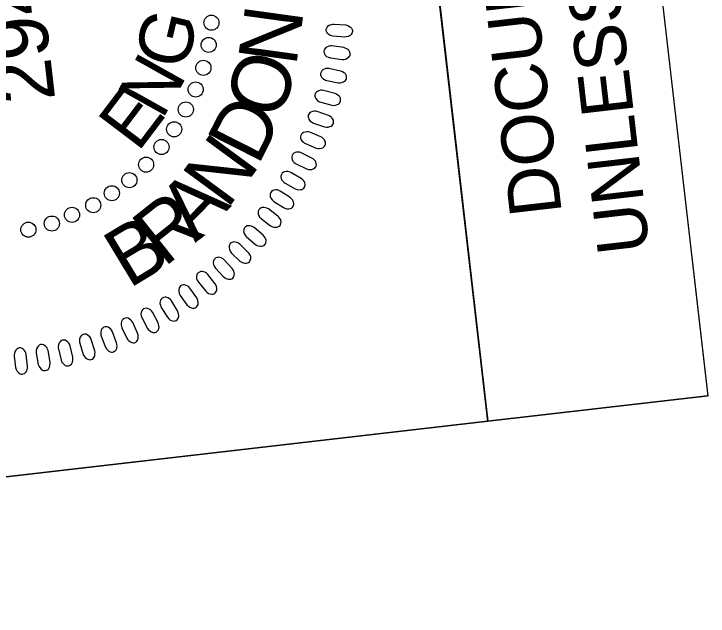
# Model space of a CAD drawing. Extents: x 477607 to 479438, y 495543 to 499482.
# Drawn here: x 477755.3 to 477829, y 497193.8 to 497257.7 of the extents above; entities that cross this region are included whole.
import ezdxf

# ---------------------------------------------------------------- set-up
doc = ezdxf.new("R2010")
doc.units = 0
for name, color, linetype in [('Sheet Border Standard 30in CELL', 7, 'Continuous'), ('Sheet Layout Plan Border', 7, 'Continuous'), ('Sheet PE Seal Cell', 7, 'Continuous'), ('Sheet Plan CELL', 7, 'Continuous'), ('Sheet Sticker Exception Certification CELL', 7, 'Continuous')]:
    doc.layers.add(name, color=color, linetype=linetype)

msp = doc.modelspace()

# ---------------------------------------------------------------- linework, layer by layer
at = {"layer": 'Sheet Border Standard 30in CELL'}
msp.add_lwpolyline([(477693.829, 497201.611), (477682.369, 497301.002), (477794.128, 497313.888), (477805.588, 497214.497)], close=True, dxfattribs=at)
at = {"layer": 'Sheet Layout Plan Border'}
msp.add_lwpolyline([(478060.611, 495968.966), (478655.257, 496063.069), (478848.534, 496026.024), (478735.995, 497002.058), (478709.928, 496998.314), (478420.128, 496964.9), (478384.13, 497277.103), (478673.93, 497310.517), (478699.758, 497316.337), (478696.236, 497346.887), (478616.747, 497337.721), (478607.505, 497417.875), (478188.47, 497393.351), (477955.381, 497379.709), (477811.168, 497371.269), (477828.931, 497217.213), (477697.933, 497202.084), (477716.324, 497043.314), (477674.836, 497038.508), (477805.454, 495905.894)], close=True, dxfattribs=at)
msp.add_lwpolyline([(478060.611, 495968.966), (478655.257, 496063.069), (478848.534, 496026.024), (478735.995, 497002.058), (478709.928, 496998.314), (478420.128, 496964.9), (478384.13, 497277.103), (478673.93, 497310.517), (478699.758, 497316.337), (478696.236, 497346.887), (478616.747, 497337.721), (478607.505, 497417.875), (478188.47, 497393.351), (477955.381, 497379.709), (477811.168, 497371.269), (477828.931, 497217.213), (477697.933, 497202.084), (477716.324, 497043.314), (477674.836, 497038.508), (477805.454, 495905.894)], close=True, dxfattribs=at)
at = {"layer": 'Sheet PE Seal Cell'}
for points in [[(477789.283, 497256.661), (477790.507, 497256.57), (477790.722, 497256.517), (477790.858, 497256.454), (477791.019, 497256.33), (477791.121, 497256.224), (477791.192, 497256.107), (477791.225, 497256), (477791.236, 497255.886), (477791.208, 497255.776), (477791.169, 497255.659), (477791.102, 497255.559), (477790.995, 497255.462), (477790.911, 497255.408), (477790.756, 497255.352), (477790.573, 497255.306), (477790.412, 497255.295), (477789.159, 497255.381), (477788.991, 497255.416), (477788.855, 497255.471), (477788.703, 497255.572), (477788.572, 497255.694), (477788.499, 497255.797), (477788.451, 497255.958), (477788.443, 497256.109), (477788.494, 497256.254), (477788.551, 497256.356), (477788.659, 497256.475), (477788.837, 497256.581), (477789.022, 497256.635), (477789.152, 497256.655)], [(477788.904, 497253.072), (477790.12, 497252.904), (477790.341, 497252.912), (477790.487, 497252.944), (477790.671, 497253.032), (477790.793, 497253.113), (477790.887, 497253.214), (477790.941, 497253.312), (477790.976, 497253.42), (477790.971, 497253.534), (477790.957, 497253.657), (477790.913, 497253.768), (477790.828, 497253.885), (477790.758, 497253.956), (477790.618, 497254.042), (477790.449, 497254.126), (477790.294, 497254.17), (477789.05, 497254.35), (477788.879, 497254.35), (477788.734, 497254.324), (477788.564, 497254.257), (477788.411, 497254.166), (477788.318, 497254.08), (477788.237, 497253.933), (477788.198, 497253.788), (477788.217, 497253.633), (477788.252, 497253.523), (477788.333, 497253.384), (477788.485, 497253.242), (477788.654, 497253.151), (477788.778, 497253.104)], [(477788.503, 497250.677), (477789.705, 497250.434), (477789.928, 497250.427), (477790.075, 497250.45), (477790.264, 497250.526), (477790.39, 497250.6), (477790.491, 497250.695), (477790.55, 497250.788), (477790.592, 497250.895), (477790.595, 497251.009), (477790.589, 497251.132), (477790.552, 497251.246), (477790.474, 497251.369), (477790.408, 497251.443), (477790.275, 497251.539), (477790.111, 497251.633), (477789.959, 497251.687), (477788.729, 497251.943), (477788.558, 497251.955), (477788.412, 497251.938), (477788.238, 497251.882), (477788.079, 497251.8), (477787.981, 497251.72), (477787.892, 497251.579), (477787.842, 497251.436), (477787.852, 497251.281), (477787.881, 497251.169), (477787.952, 497251.025), (477788.095, 497250.874), (477788.258, 497250.772), (477788.379, 497250.718)], [(477787.859, 497248.38), (477789.044, 497248.061), (477789.266, 497248.04), (477789.414, 497248.054), (477789.608, 497248.119), (477789.739, 497248.184), (477789.844, 497248.272), (477789.91, 497248.362), (477789.959, 497248.466), (477789.968, 497248.579), (477789.97, 497248.703), (477789.941, 497248.819), (477789.87, 497248.946), (477789.809, 497249.024), (477789.682, 497249.128), (477789.525, 497249.232), (477789.376, 497249.296), (477788.164, 497249.629), (477787.995, 497249.651), (477787.849, 497249.643), (477787.671, 497249.599), (477787.507, 497249.527), (477787.405, 497249.453), (477787.306, 497249.318), (477787.248, 497249.178), (477787.249, 497249.024), (477787.27, 497248.91), (477787.332, 497248.761), (477787.465, 497248.602), (477787.622, 497248.49), (477787.739, 497248.428)], [(477787.102, 497246.151), (477788.264, 497245.759), (477788.484, 497245.724), (477788.633, 497245.729), (477788.83, 497245.781), (477788.965, 497245.838), (477789.076, 497245.918), (477789.147, 497246.004), (477789.202, 497246.105), (477789.218, 497246.217), (477789.229, 497246.34), (477789.206, 497246.458), (477789.144, 497246.59), (477789.088, 497246.672), (477788.968, 497246.783), (477788.817, 497246.898), (477788.673, 497246.97), (477787.485, 497247.379), (477787.316, 497247.411), (477787.17, 497247.413), (477786.99, 497247.38), (477786.822, 497247.318), (477786.715, 497247.251), (477786.608, 497247.122), (477786.541, 497246.986), (477786.531, 497246.832), (477786.546, 497246.717), (477786.599, 497246.565), (477786.721, 497246.398), (477786.871, 497246.276), (477786.984, 497246.207)], [(477786.238, 497243.978), (477787.374, 497243.514), (477787.591, 497243.465), (477787.74, 497243.46), (477787.94, 497243.5), (477788.078, 497243.549), (477788.194, 497243.622), (477788.271, 497243.704), (477788.332, 497243.801), (477788.355, 497243.911), (477788.373, 497244.033), (477788.358, 497244.153), (477788.304, 497244.288), (477788.254, 497244.373), (477788.14, 497244.492), (477787.997, 497244.616), (477787.858, 497244.697), (477786.697, 497245.179), (477786.532, 497245.222), (477786.385, 497245.234), (477786.204, 497245.211), (477786.032, 497245.161), (477785.922, 497245.101), (477785.807, 497244.978), (477785.732, 497244.847), (477785.713, 497244.694), (477785.719, 497244.578), (477785.763, 497244.422), (477785.875, 497244.248), (477786.016, 497244.117), (477786.124, 497244.041)], [(477785.262, 497241.834), (477786.367, 497241.3), (477786.58, 497241.237), (477786.728, 497241.223), (477786.93, 497241.25), (477787.071, 497241.29), (477787.191, 497241.356), (477787.274, 497241.433), (477787.34, 497241.526), (477787.371, 497241.635), (477787.397, 497241.756), (477787.388, 497241.876), (477787.344, 497242.013), (477787.298, 497242.102), (477787.193, 497242.228), (477787.057, 497242.36), (477786.924, 497242.45), (477785.796, 497243.004), (477785.633, 497243.058), (477785.488, 497243.078), (477785.305, 497243.067), (477785.131, 497243.027), (477785.017, 497242.974), (477784.894, 497242.859), (477784.812, 497242.733), (477784.782, 497242.581), (477784.781, 497242.465), (477784.815, 497242.308), (477784.916, 497242.126), (477785.049, 497241.987), (477785.152, 497241.904)], [(477784.076, 497239.783), (477785.145, 497239.18), (477785.354, 497239.105), (477785.501, 497239.082), (477785.704, 497239.096), (477785.848, 497239.127), (477785.972, 497239.185), (477786.058, 497239.256), (477786.131, 497239.345), (477786.168, 497239.452), (477786.201, 497239.571), (477786.201, 497239.692), (477786.165, 497239.832), (477786.125, 497239.923), (477786.027, 497240.055), (477785.901, 497240.195), (477785.773, 497240.293), (477784.682, 497240.917), (477784.524, 497240.981), (477784.38, 497241.01), (477784.197, 497241.011), (477784.02, 497240.983), (477783.903, 497240.937), (477783.773, 497240.83), (477783.682, 497240.709), (477783.644, 497240.559), (477783.636, 497240.443), (477783.66, 497240.284), (477783.749, 497240.097), (477783.873, 497239.949), (477783.971, 497239.86)], [(477782.889, 497237.853), (477783.917, 497237.184), (477784.122, 497237.096), (477784.267, 497237.063), (477784.47, 497237.065), (477784.615, 497237.087), (477784.743, 497237.137), (477784.834, 497237.203), (477784.912, 497237.287), (477784.956, 497237.391), (477784.996, 497237.508), (477785.003, 497237.628), (477784.976, 497237.771), (477784.943, 497237.864), (477784.854, 497238.002), (477784.736, 497238.15), (477784.614, 497238.256), (477783.565, 497238.947), (477783.41, 497239.021), (477783.268, 497239.059), (477783.086, 497239.071), (477782.908, 497239.054), (477782.788, 497239.015), (477782.653, 497238.916), (477782.554, 497238.802), (477782.506, 497238.655), (477782.491, 497238.539), (477782.505, 497238.379), (477782.582, 497238.187), (477782.696, 497238.031), (477782.788, 497237.936)], [(477781.562, 497235.999), (477782.547, 497235.267), (477782.745, 497235.166), (477782.888, 497235.125), (477783.091, 497235.113), (477783.238, 497235.126), (477783.368, 497235.168), (477783.462, 497235.228), (477783.545, 497235.307), (477783.596, 497235.408), (477783.643, 497235.523), (477783.658, 497235.642), (477783.64, 497235.785), (477783.612, 497235.881), (477783.533, 497236.025), (477783.424, 497236.179), (477783.31, 497236.293), (477782.305, 497237.049), (477782.156, 497237.132), (477782.017, 497237.179), (477781.836, 497237.202), (477781.657, 497237.196), (477781.535, 497237.165), (477781.393, 497237.075), (477781.287, 497236.967), (477781.231, 497236.823), (477781.209, 497236.709), (477781.212, 497236.548), (477781.277, 497236.351), (477781.381, 497236.189), (477781.467, 497236.088)], [(477779.994, 497234.072), (477780.931, 497233.279), (477781.122, 497233.166), (477781.262, 497233.115), (477781.465, 497233.091), (477781.611, 497233.095), (477781.745, 497233.129), (477781.843, 497233.183), (477781.93, 497233.256), (477781.987, 497233.355), (477782.042, 497233.465), (477782.064, 497233.583), (477782.055, 497233.728), (477782.033, 497233.825), (477781.962, 497233.973), (477781.864, 497234.135), (477781.757, 497234.255), (477780.802, 497235.072), (477780.658, 497235.165), (477780.522, 497235.22), (477780.343, 497235.256), (477780.164, 497235.26), (477780.041, 497235.237), (477779.893, 497235.156), (477779.781, 497235.054), (477779.715, 497234.915), (477779.686, 497234.803), (477779.68, 497234.641), (477779.732, 497234.441), (477779.826, 497234.273), (477779.905, 497234.167)], [(477778.409, 497232.369), (477779.294, 497231.519), (477779.477, 497231.394), (477779.614, 497231.335), (477779.814, 497231.298), (477779.961, 497231.292), (477780.096, 497231.318), (477780.197, 497231.366), (477780.289, 497231.433), (477780.352, 497231.527), (477780.413, 497231.635), (477780.443, 497231.751), (477780.443, 497231.896), (477780.427, 497231.994), (477780.366, 497232.147), (477780.278, 497232.314), (477780.179, 497232.441), (477779.277, 497233.317), (477779.14, 497233.418), (477779.007, 497233.482), (477778.831, 497233.528), (477778.652, 497233.544), (477778.527, 497233.529), (477778.375, 497233.457), (477778.257, 497233.363), (477778.183, 497233.228), (477778.146, 497233.118), (477778.13, 497232.957), (477778.169, 497232.753), (477778.252, 497232.58), (477778.325, 497232.469)], [(477776.7, 497230.759), (477777.53, 497229.855), (477777.706, 497229.719), (477777.839, 497229.651), (477778.036, 497229.602), (477778.182, 497229.587), (477778.318, 497229.604), (477778.422, 497229.646), (477778.519, 497229.707), (477778.588, 497229.797), (477778.656, 497229.9), (477778.692, 497230.015), (477778.702, 497230.159), (477778.692, 497230.259), (477778.64, 497230.414), (477778.563, 497230.587), (477778.472, 497230.72), (477777.627, 497231.65), (477777.496, 497231.76), (477777.368, 497231.832), (477777.194, 497231.889), (477777.018, 497231.916), (477776.892, 497231.91), (477776.736, 497231.848), (477776.612, 497231.761), (477776.529, 497231.63), (477776.486, 497231.523), (477776.459, 497231.363), (477776.486, 497231.158), (477776.558, 497230.98), (477776.623, 497230.864)], [(477774.884, 497229.265), (477775.656, 497228.31), (477775.823, 497228.163), (477775.951, 497228.088), (477776.145, 497228.026), (477776.289, 497228.002), (477776.427, 497228.011), (477776.533, 497228.045), (477776.633, 497228.1), (477776.707, 497228.187), (477776.782, 497228.285), (477776.826, 497228.397), (477776.844, 497228.541), (477776.841, 497228.64), (477776.799, 497228.799), (477776.732, 497228.976), (477776.65, 497229.114), (477775.866, 497230.096), (477775.742, 497230.214), (477775.618, 497230.294), (477775.449, 497230.362), (477775.274, 497230.4), (477775.148, 497230.401), (477774.988, 497230.349), (477774.859, 497230.27), (477774.768, 497230.145), (477774.718, 497230.041), (477774.682, 497229.883), (477774.696, 497229.676), (477774.756, 497229.494), (477774.815, 497229.375)], [(477772.956, 497227.878), (477773.666, 497226.877), (477773.823, 497226.721), (477773.947, 497226.637), (477774.136, 497226.563), (477774.279, 497226.53), (477774.416, 497226.53), (477774.525, 497226.558), (477774.628, 497226.607), (477774.707, 497226.688), (477774.788, 497226.782), (477774.839, 497226.891), (477774.866, 497227.033), (477774.869, 497227.133), (477774.837, 497227.293), (477774.782, 497227.474), (477774.709, 497227.618), (477773.987, 497228.647), (477773.87, 497228.772), (477773.753, 497228.86), (477773.588, 497228.938), (477773.416, 497228.987), (477773.29, 497228.996), (477773.128, 497228.954), (477772.994, 497228.883), (477772.895, 497228.764), (477772.838, 497228.663), (477772.793, 497228.508), (477772.794, 497228.301), (477772.842, 497228.115), (477772.893, 497227.992)], [(477770.941, 497226.592), (477771.587, 497225.548), (477771.734, 497225.382), (477771.852, 497225.29), (477772.037, 497225.206), (477772.177, 497225.163), (477772.315, 497225.154), (477772.424, 497225.176), (477772.53, 497225.218), (477772.615, 497225.294), (477772.701, 497225.382), (477772.759, 497225.488), (477772.795, 497225.628), (477772.804, 497225.727), (477772.782, 497225.89), (477772.738, 497226.074), (477772.674, 497226.221), (477772.019, 497227.294), (477771.91, 497227.426), (477771.799, 497227.521), (477771.639, 497227.609), (477771.47, 497227.67), (477771.345, 497227.686), (477771.18, 497227.655), (477771.042, 497227.593), (477770.937, 497227.48), (477770.874, 497227.382), (477770.818, 497227.231), (477770.806, 497227.024), (477770.843, 497226.836), (477770.886, 497226.71)], [(477768.899, 497225.451), (477769.478, 497224.369), (477769.615, 497224.193), (477769.726, 497224.094), (477769.905, 497223.998), (477770.043, 497223.947), (477770.18, 497223.93), (477770.29, 497223.944), (477770.399, 497223.979), (477770.488, 497224.05), (477770.579, 497224.133), (477770.643, 497224.234), (477770.688, 497224.372), (477770.704, 497224.47), (477770.692, 497224.635), (477770.66, 497224.82), (477770.605, 497224.972), (477770.019, 497226.083), (477769.919, 497226.223), (477769.813, 497226.324), (477769.659, 497226.422), (477769.494, 497226.493), (477769.371, 497226.517), (477769.204, 497226.496), (477769.063, 497226.443), (477768.95, 497226.337), (477768.881, 497226.244), (477768.816, 497226.096), (477768.791, 497225.89), (477768.816, 497225.7), (477768.851, 497225.572)], [(477766.764, 497224.441), (477767.274, 497223.325), (477767.399, 497223.141), (477767.504, 497223.035), (477767.677, 497222.928), (477767.811, 497222.868), (477767.946, 497222.843), (477768.057, 497222.85), (477768.168, 497222.878), (477768.261, 497222.943), (477768.358, 497223.02), (477768.428, 497223.118), (477768.481, 497223.252), (477768.503, 497223.349), (477768.502, 497223.513), (477768.482, 497223.702), (477768.436, 497223.856), (477767.92, 497225.002), (477767.829, 497225.147), (477767.73, 497225.255), (477767.583, 497225.363), (477767.423, 497225.443), (477767.301, 497225.476), (477767.134, 497225.465), (477766.989, 497225.421), (477766.87, 497225.322), (477766.795, 497225.234), (477766.721, 497225.09), (477766.683, 497224.886), (477766.696, 497224.695), (477766.723, 497224.565)], [(477764.57, 497223.53), (477765.008, 497222.384), (477765.122, 497222.193), (477765.22, 497222.08), (477765.386, 497221.962), (477765.516, 497221.895), (477765.649, 497221.861), (477765.761, 497221.861), (477765.873, 497221.882), (477765.97, 497221.941), (477766.071, 497222.011), (477766.148, 497222.104), (477766.21, 497222.236), (477766.237, 497222.331), (477766.247, 497222.495), (477766.238, 497222.684), (477766.202, 497222.841), (477765.76, 497224.017), (477765.678, 497224.168), (477765.586, 497224.282), (477765.445, 497224.399), (477765.291, 497224.489), (477765.172, 497224.529), (477765.003, 497224.529), (477764.856, 497224.494), (477764.731, 497224.403), (477764.651, 497224.319), (477764.568, 497224.18), (477764.518, 497223.98), (477764.518, 497223.787), (477764.538, 497223.656)], [(477762.299, 497222.785), (477762.665, 497221.614), (477762.766, 497221.416), (477762.857, 497221.298), (477763.015, 497221.169), (477763.141, 497221.094), (477763.271, 497221.051), (477763.383, 497221.045), (477763.496, 497221.059), (477763.597, 497221.111), (477763.702, 497221.176), (477763.785, 497221.264), (477763.854, 497221.391), (477763.888, 497221.484), (477763.908, 497221.647), (477763.911, 497221.837), (477763.885, 497221.995), (477763.517, 497223.197), (477763.445, 497223.352), (477763.36, 497223.472), (477763.227, 497223.597), (477763.078, 497223.697), (477762.962, 497223.745), (477762.795, 497223.755), (477762.645, 497223.729), (477762.515, 497223.647), (477762.43, 497223.568), (477762.338, 497223.435), (477762.275, 497223.237), (477762.264, 497223.045), (477762.275, 497222.913)], [(477760.027, 497222.187), (477760.318, 497220.996), (477760.407, 497220.792), (477760.491, 497220.668), (477760.64, 497220.53), (477760.761, 497220.447), (477760.889, 497220.396), (477761, 497220.383), (477761.114, 497220.39), (477761.217, 497220.436), (477761.327, 497220.493), (477761.415, 497220.576), (477761.492, 497220.698), (477761.531, 497220.79), (477761.561, 497220.951), (477761.576, 497221.14), (477761.56, 497221.3), (477761.269, 497222.522), (477761.207, 497222.681), (477761.129, 497222.806), (477761.005, 497222.94), (477760.863, 497223.049), (477760.75, 497223.104), (477760.583, 497223.124), (477760.433, 497223.108), (477760.297, 497223.034), (477760.207, 497222.96), (477760.107, 497222.833), (477760.032, 497222.64), (477760.009, 497222.45), (477760.011, 497222.317)], [(477755.344, 497221.429), (477755.484, 497220.21), (477755.547, 497219.997), (477755.614, 497219.864), (477755.745, 497219.708), (477755.854, 497219.61), (477755.975, 497219.544), (477756.083, 497219.516), (477756.197, 497219.509), (477756.306, 497219.542), (477756.421, 497219.585), (477756.519, 497219.656), (477756.611, 497219.768), (477756.661, 497219.854), (477756.711, 497220.01), (477756.75, 497220.195), (477756.754, 497220.356), (477756.618, 497221.606), (477756.577, 497221.771), (477756.516, 497221.905), (477756.408, 497222.053), (477756.281, 497222.179), (477756.176, 497222.247), (477756.013, 497222.289), (477755.862, 497222.291), (477755.718, 497222.234), (477755.62, 497222.173), (477755.504, 497222.06), (477755.405, 497221.878), (477755.359, 497221.692), (477755.344, 497221.559)], [(477757.68, 497221.751), (477757.896, 497220.543), (477757.972, 497220.334), (477758.048, 497220.206), (477758.189, 497220.059), (477758.304, 497219.967), (477758.428, 497219.909), (477758.538, 497219.888), (477758.652, 497219.889), (477758.758, 497219.928), (477758.871, 497219.979), (477758.964, 497220.056), (477759.049, 497220.173), (477759.094, 497220.262), (477759.133, 497220.42), (477759.161, 497220.608), (477759.155, 497220.768), (477758.94, 497222.007), (477758.888, 497222.17), (477758.82, 497222.299), (477758.703, 497222.441), (477758.568, 497222.558), (477758.459, 497222.62), (477758.294, 497222.651), (477758.143, 497222.644), (477758.003, 497222.579), (477757.908, 497222.511), (477757.801, 497222.391), (477757.713, 497222.203), (477757.679, 497222.014), (477757.672, 497221.881)]]:
    msp.add_lwpolyline(points, close=True, dxfattribs=at)
for centre in [(477776.264, 497256.812), (477775.974, 497254.454), (477775.411, 497252.025), (477774.592, 497249.727), (477773.553, 497247.603), (477772.312, 497245.497), (477770.964, 497243.619), (477769.334, 497241.748), (477767.559, 497240.101), (477765.702, 497238.711), (477763.723, 497237.441), (477761.474, 497236.421), (477759.335, 497235.494), (477756.843, 497234.847)]:
    msp.add_circle(centre, 0.801, dxfattribs=at)
at = {"layer": 'Sheet Plan CELL'}
for points in [[(478848.516, 496026.186), (477805.454, 495905.894), (477656.512, 497197.321), (477805.585, 497214.522), (477782.685, 497413.244), (478676.699, 497516.326)], [(477693.84, 497201.625), (477682.38, 497301.016), (477794.152, 497313.904), (477805.585, 497214.522)]]:
    msp.add_lwpolyline(points, close=True, dxfattribs=at)
at = {"layer": 'Sheet Sticker Exception Certification CELL'}
for p, q in [((477806.018, 497415.934), (477828.931, 497217.213)), ((477806.021, 497415.909), (477828.934, 497217.189)), ((477805.588, 497214.497), (477782.675, 497413.218)), ((477828.931, 497217.213), (477805.585, 497214.522)), ((477828.934, 497217.189), (477805.588, 497214.497))]:
    msp.add_line(p, q, dxfattribs=at)

# ---------------------------------------------------------------- texts
at = {"layer": 'Sheet PE Seal Cell'}
for s, height, rotation, p in [('29470', 6.2363, 96.55865, (477759.704, 497248.641)), ('N', 6.236, 82.12779, (477785.247, 497252.101)), ('G', 5.669, 76.66226, (477773.564, 497251.648)), ('N', 5.669, 60.78267, (477771.046, 497246.431)), ('O', 6.236, 72.02794, (477783.527, 497246.314)), ('E', 5.669, 52.84287, (477768.47, 497242.978)), ('D', 6.236, 63.15972, (477781.2, 497241.549)), ('N', 6.236, 53.67003, (477777.928, 497236.915)), ('A', 6.236, 45.55885, (477774.557, 497233.426)), ('R', 6.236, 38.44201, (477771.22, 497230.784)), ('B', 6.236, 31.16698, (477767.497, 497228.532))]:
    msp.add_text(s, height=height, rotation=rotation, dxfattribs=at).set_placement(p)
at = {"layer": 'Sheet Sticker Exception Certification CELL'}
for s, p in [('UNLESS ALL SIGNATURES COMPLETED', (477822.772, 497232.609)), ('UNLESS ALL SIGNATURES COMPLETED', (477822.775, 497232.584)), ('DOCUMENT NOT CONSIDERED FINAL', (477813.449, 497236.639)), ('DOCUMENT NOT CONSIDERED FINAL', (477813.452, 497236.614))]:
    msp.add_text(s, height=5.5, rotation=96.57729, dxfattribs=at).set_placement(p)

doc.saveas('drawing.dxf')
